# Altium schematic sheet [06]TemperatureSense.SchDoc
size A4; SheetNumber: 5; SheetTotal: 5
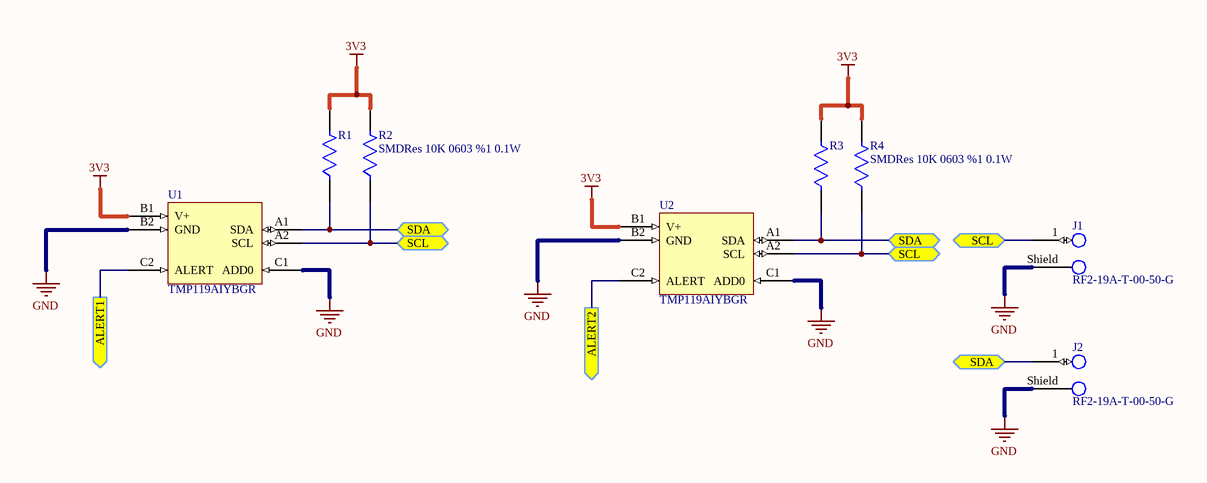
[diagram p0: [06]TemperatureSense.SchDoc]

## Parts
J1  RF2-19A-T-00-50-G  [RF2-19A-T-00-50-G]
J2  RF2-19A-T-00-50-G  [RF2-19A-T-00-50-G]
R1  SMDRes 10K 0603 %1 0.1W  [RESC1508X06N]  (value not drawn)
R2  SMDRes 10K 0603 %1 0.1W  [RESC1508X06N]
R3  SMDRes 10K 0603 %1 0.1W  [RESC1508X06N]  (value not drawn)
R4  SMDRes 10K 0603 %1 0.1W  [RESC1508X06N]
U1  TMP119AIYBGR  [BGA6C40P2X3_95X149X52]
U2  TMP119AIYBGR  [BGA6C40P2X3_95X149X52]

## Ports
ALERT1 (out), ALERT2 (out), SCL (bidir, see [06]TemperatureSense[2C], [06]TemperatureSense[4C]), SCL (bidir, see [06]TemperatureSense[4C]), SDA (bidir, see [06]TemperatureSense[2B], [06]TemperatureSense[4C]), SDA (bidir, see [06]TemperatureSense[4C])

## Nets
3V3: R1.2 R2.2 R3.2 R4.2 U1.B1(V+) U2.B1(V+)
GND: J1.Shield J2.Shield U1.B2(GND) U1.C1(ADD0) U2.B2(GND) U2.C1(ADD0)
ALERT1: U1.C2(ALERT) ; port ALERT1
ALERT2: U2.C2(ALERT) ; port ALERT2
SCL: J1.1 R2.1 R4.1 U1.A2(SCL) U2.A2(SCL) ; port SCL
SDA: J2.1 R1.1 R3.1 U1.A1(SDA) U2.A1(SDA) ; port SDA

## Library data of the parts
J1 J2 = CMP-00025-2: Rf Sma Connector
R1-R4 = CMP-00001-1-2: Res Thick Film 0603 10K Ohm 1% 0.1W(1/10W) ±100ppm/C Pad SMD T/R Automotive AEC-Q200; Manufacturer Number: RMCF0603FT10K0; Manufacturer: Stackpole Electronics Inc
U1 U2 = CMP-00021-1: Temperature Sensor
